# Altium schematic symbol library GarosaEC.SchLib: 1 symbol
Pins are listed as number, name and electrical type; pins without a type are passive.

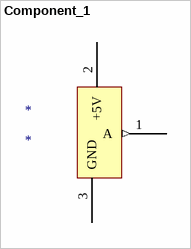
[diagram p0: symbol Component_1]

## Component_1
designator *
pins: 1 A (out), 2 +5V (power), 3 GND (power)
